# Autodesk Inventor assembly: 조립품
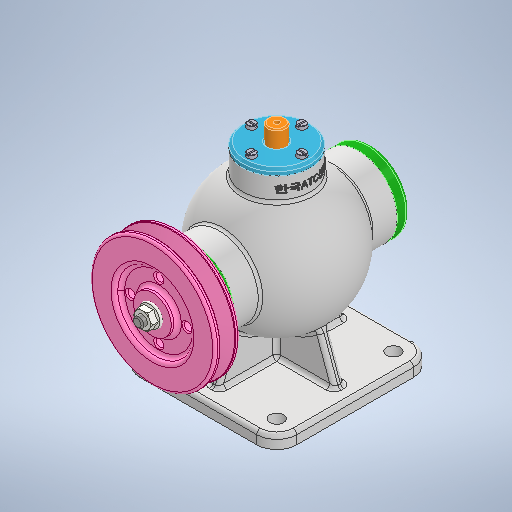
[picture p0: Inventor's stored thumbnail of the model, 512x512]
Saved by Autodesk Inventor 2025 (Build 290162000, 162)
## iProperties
Created: 2024-07
Part Number: 조립품
Document SubType Name: Assembly
Designer: myung
Author: myung
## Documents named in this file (15)
- C:\Users\myung\OneDrive\바탕 화면\740708V1007\조립품.iam
- C:\Users\myung\OneDrive\바탕 화면\740708V1007\본체.ipt
- C:\Users\myung\OneDrive\바탕 화면\740708V1007\뒤커버\뒤커버.ipt
- C:\Users\myung\OneDrive\바탕 화면\740708V1007\앞커버\앞커버.ipt
- C:\Users\myung\OneDrive\바탕 화면\740708V1007\상부커버\상부커버.ipt
- C:\Users\myung\OneDrive\바탕 화면\740708V1007\베어링- 6202\베어링- 6202.ipt
- C:\Users\myung\OneDrive\바탕 화면\740708V1007\칼라\칼라.ipt
- C:\Users\myung\OneDrive\바탕 화면\740708V1007\편심축\편심축.ipt
- C:\Users\myung\OneDrive\바탕 화면\740708V1007\키 4 x 4 x 12\키 4 x 4 x 12.ipt
- C:\Users\myung\OneDrive\바탕 화면\740708V1007\오일실 15 30 7\오일실 15 30 7.ipt
- C:\Users\myung\OneDrive\바탕 화면\740708V1007\볼트 M4 x 16\볼트 M4 x 16.ipt
- C:\Users\myung\OneDrive\바탕 화면\740708V1007\V-벨트풀리\V-벨트풀리.ipt
- C:\Users\myung\OneDrive\바탕 화면\740708V1007\너트 M8\너트 M8.ipt
- C:\Users\myung\OneDrive\바탕 화면\740708V1007\볼트 M4 x 12\볼트 M4 x 12.ipt
- C:\Users\myung\OneDrive\바탕 화면\740708V1007\슬라이드\슬라이드.ipt
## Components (1 placed, 1 different names)
1. V-벨트풀리:1
